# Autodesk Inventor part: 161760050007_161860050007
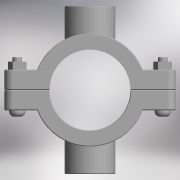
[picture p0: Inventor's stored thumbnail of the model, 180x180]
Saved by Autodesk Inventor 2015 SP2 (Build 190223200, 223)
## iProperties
Created: 2017-05
Part Number: 161760050007_161860050007
Material: Generic
Description: PLASSON DOUBLE SADDLE 50-3/4"
Document SubType Name: Modeling
Designer: KIM
Density: 1 g/cm^3
Appearance: Default
Author: KIM
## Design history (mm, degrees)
derived "16176.ipt"
feature "Solid1::16176.ipt"
feature "Solid2::16176.ipt"
tag "TaggingFeature1"
body "Solid1"
body "Solid2"
other parameters: "d1" = 106, "d2" = 25, "d4" = 73, "d5" = 0, "d6" = 5.3, "d7" = 106, "d8" = 0.1, "d10" = 0, "d11" = 0.5, "d20" = 0.5, "d23" = 0.5, "d37" = 8, "d38" = 33, "d39" = 0, "d40" = 3, "d41" = 5, "d42" = 0, "d43" = 6, "d44" = 3, "d45" = 0, "d46" = 0.5, "d52" = 24.117, "d53" = 19, "d54" = 0, "d55" = 21, "d57" = 0, "d58" = 54, "d60" = 0, "d63" = 36.5, "d66" = 0, "d67" = 104, "d68" = 31.3521, "d69" = 24.117, "d70" = 19, "d71" = 0, "d72" = 21, "d74" = 0, "d75" = 0.5, "B_" = 21, "G_" = 24.117, "A_" = 52, "L_" = 106, "L_1" = 73, "l_2" = 19
